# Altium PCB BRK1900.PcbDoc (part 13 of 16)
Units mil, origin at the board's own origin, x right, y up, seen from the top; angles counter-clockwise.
Board outline 8858.27 x 5905.51 mil, 10 copper layers (L1-TOP, L2-GND, L3-PWR, L4-GND, L5-PWR, L6-PWR, L7-GND, L8-SIG, L9-GND, L10-BOT), stack 48.824 mil thick; 456 components, 571 nets, 2296 pads, 2416 vias.
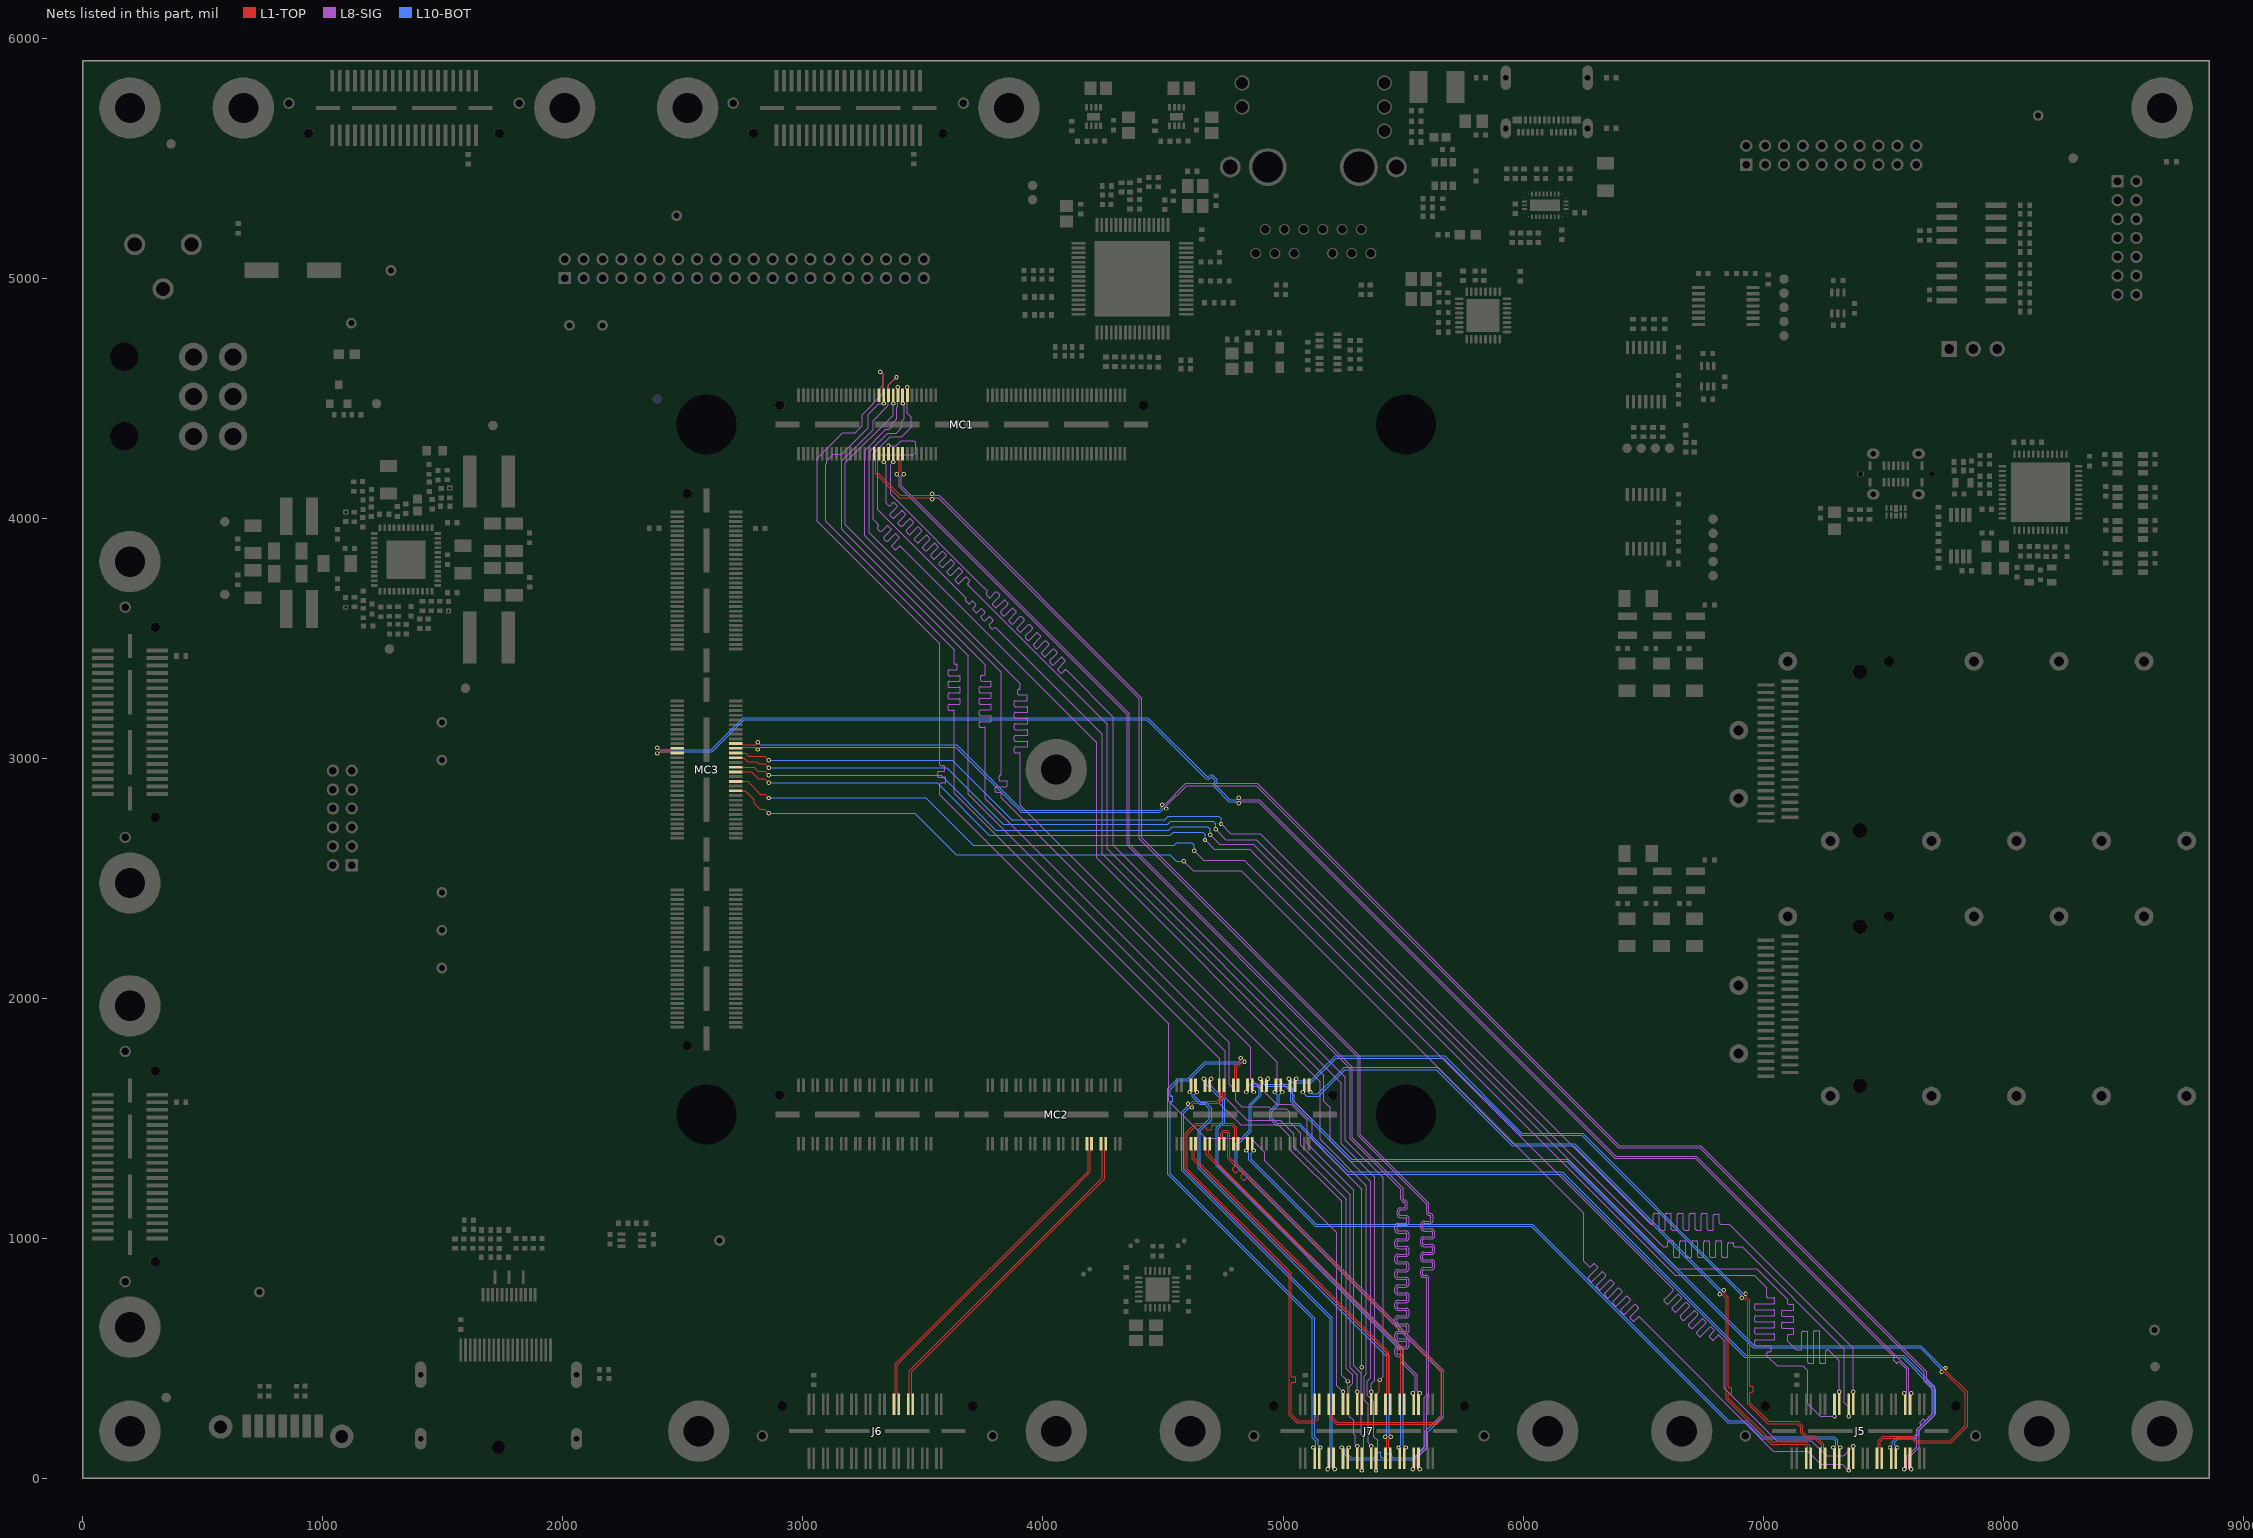
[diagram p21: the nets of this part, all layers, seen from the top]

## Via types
v1: diameter 18, hole 10, L1-TOP to L10-BOT, tented both sides, 2170 vias
v2: diameter 20, hole 10, L1-TOP to L10-BOT, tented both sides, 246 vias

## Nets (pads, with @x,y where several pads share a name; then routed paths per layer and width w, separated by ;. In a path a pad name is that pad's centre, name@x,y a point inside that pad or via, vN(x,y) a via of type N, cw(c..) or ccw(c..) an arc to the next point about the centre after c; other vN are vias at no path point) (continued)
SZG_PORTE_TX2N: J6.32 MC2.76 | length 1421.5
  L1-TOP w3.3: J6.32@3458.22,309.84 3458.22,349.17 3452.88,354.51 3452.88,445.15 4120.36,1112.64 4256.47,1248.74 4256.47,1365.8 4261.81,1371.14 MC2.76@4261.81,1394.09
SZG_PORTE_TX2P: J6.30 MC2.74 | length 1421.5
  L1-TOP w3.3: J6.30@3438.53,309.84 3438.53,349.4 3443.88,354.74 3443.88,448.88 4247.47,1252.47 4247.47,1365.74 4242.13,1371.08 MC2.74@4242.13,1394.09
SZG_PORTE_TX3N: J6.28 MC2.72 | length 1421.5
  L1-TOP w3.3: J6.28@3399.16,309.84 3399.16,349.57 3393.82,354.91 3393.82,473.09 4111.73,1191 4197.41,1276.69 4197.41,1365.35 4202.76,1370.69 MC2.72@4202.76,1394.09
SZG_PORTE_TX3P: J6.26 MC2.70 | length 1420.4
  L1-TOP w3.3: J6.26@3379.48,309.84 3379.48,349 3384.82,354.34 3384.82,451.57 ; 3384.82,452.73 3384.82,476.82 4188.41,1280.41 4188.41,1365.85 4183.07,1371.2 MC2.70@4183.07,1394.09
SZG_PORTF_C2P_CLKN: J7.36 MC1.46 | length 5620
  L1-TOP w3.3: MC1.46@3415.35,4268.11 3411.77,4264.53 3411.77,4241.56 3410.01,4239.8 3410.01,4192.39 v1@3419.29,4183.11
  L8-SIG w3.15: v1@3419.29,4183.11 3410.01,4173.83 3410.01,4133.99 4359,3185 4359,2640.73 5285.89,1713.84 5288.53,1711.2 5288.53,1419.2 5500,1207.73 5500,1188.98 5500,1164.19 ccw(c5504.63,1164.19) 5504.63,1159.56 cw(c5504.63,1145.93) 5518.26,1145.93 5518.26,1132.04 cw(c5504.63,1132.04) 5504.63,1118.41 5489.22,1118.41 ccw(c5489.22,1113.78) 5484.59,1113.78 5484.59,1099.89 ccw(c5489.22,1099.89) 5489.22,1095.26 5511.37,1095.26 cw(c5511.37,1081.63) 5525,1081.63 5525,1067.74 cw(c5511.37,1067.74) 5511.37,1054.11 5479.63,1054.11 ccw(c5479.63,1049.48) 5475,1049.48 5475,1035.59 ccw(c5479.63,1035.59) 5479.63,1030.96 5511.37,1030.96 cw(c5511.37,1017.33) 5525,1017.33 5525,1003.44 cw(c5511.37,1003.44) 5511.37,989.81 5479.63,989.81 ccw(c5479.63,985.18) 5475,985.18 5475,971.29 ccw(c5479.63,971.29) 5479.63,966.66 5511.37,966.66 cw(c5511.37,953.03) 5525,953.03 5525,939.14 cw(c5511.37,939.14) 5511.37,925.51 5479.63,925.51 ccw(c5479.63,920.88) 5475,920.88 5475,906.99 ccw(c5479.63,906.99) 5479.63,902.36 5511.37,902.36 cw(c5511.37,888.73) 5525,888.73 5525,874.84 cw(c5511.37,874.84) 5511.37,861.21 5479.63,861.21 ccw(c5479.63,856.58) 5475,856.58 5475,842.69 ccw(c5479.63,842.69) 5479.63,838.06 5511.37,838.06 cw(c5511.37,824.43) 5525,824.43 5525,810.54 cw(c5511.37,810.54) 5511.37,796.91 5479.63,796.91 ccw(c5479.63,792.28) 5475,792.28 5475,778.39 ccw(c5479.63,778.39) 5479.63,773.76 5511.37,773.76 cw(c5511.37,760.13) 5525,760.13 5525,746.24 cw(c5511.37,746.24) 5511.37,732.61 5479.63,732.61 ccw(c5479.63,727.98) 5475,727.98 5475,714.09 ccw(c5479.63,714.09) 5479.63,709.46 5511.37,709.46 cw(c5511.37,695.83) 5525,695.83 5525,681.94 cw(c5511.37,681.94) 5511.37,668.31 5479.63,668.31 ccw(c5479.63,663.68) 5475,663.68 5475,649.79 ccw(c5479.63,649.79) 5479.63,645.16 5511.37,645.16 cw(c5511.37,631.53) 5525,631.53 5525,617.64 cw(c5511.37,617.64) 5511.37,604.01 5479.63,604.01 ccw(c5479.63,599.38) 5475,599.38 5475,585.49 ccw(c5479.63,585.49) 5479.63,580.86 5511.37,580.86 cw(c5511.37,567.23) 5525,567.23 5525,553.34 cw(c5511.37,553.34) 5511.37,539.71 5479.63,539.71 ccw(c5479.63,535.08) 5475,535.08 5475,521.19 ccw(c5479.63,521.19) 5479.63,516.56 5486.37,516.56 cw(c5486.37,502.93) 5500,502.93 5500,496.85 5500,489.11 5559.17,429.93 5559.17,364.12 v1@5568.45,354.84
  other v1: 5569.55,354.84 3420.39,4183.11
SZG_PORTF_C2P_CLKP: J7.34 MC1.44 | length 5620
  L1-TOP w3.3: v1@3391.73,4183.11 3401.01,4192.39 3401.01,4240.16 3395.67,4245.5 MC1.44@3395.67,4268.11
  L8-SIG w3.15: v1@3391.73,4183.11 3401.01,4173.83 3401.01,4130.26 4350,3181.27 4350,2637 5279.53,1707.47 5279.53,1415.47 5491,1204 5491,1188.98 5491,1164.19 ccw(c5504.63,1164.19) 5504.63,1150.56 cw(c5504.63,1145.93) 5509.26,1145.93 5509.26,1132.04 cw(c5504.63,1132.04) 5504.63,1127.41 5489.22,1127.41 ccw(c5489.22,1113.78) 5475.59,1113.78 5475.59,1099.89 ccw(c5489.22,1099.89) 5489.22,1086.26 5511.37,1086.26 cw(c5511.37,1081.63) 5516,1081.63 5516,1067.74 cw(c5511.37,1067.74) 5511.37,1063.11 5479.63,1063.11 ccw(c5479.63,1049.48) 5466,1049.48 5466,1035.59 ccw(c5479.63,1035.59) 5479.63,1021.96 5511.37,1021.96 cw(c5511.37,1017.33) 5516,1017.33 5516,1003.44 cw(c5511.37,1003.44) 5511.37,998.81 5479.63,998.81 ccw(c5479.63,985.18) 5466,985.18 5466,971.29 ccw(c5479.63,971.29) 5479.63,957.66 5511.37,957.66 cw(c5511.37,953.03) 5516,953.03 5516,939.14 cw(c5511.37,939.14) 5511.37,934.51 5479.63,934.51 ccw(c5479.63,920.88) 5466,920.88 5466,906.99 ccw(c5479.63,906.99) 5479.63,893.36 5511.37,893.36 cw(c5511.37,888.73) 5516,888.73 5516,874.84 cw(c5511.37,874.84) 5511.37,870.21 5479.63,870.21 ccw(c5479.63,856.58) 5466,856.58 5466,842.69 ccw(c5479.63,842.69) 5479.63,829.06 5511.37,829.06 cw(c5511.37,824.43) 5516,824.43 5516,810.54 cw(c5511.37,810.54) 5511.37,805.91 5479.63,805.91 ccw(c5479.63,792.28) 5466,792.28 5466,778.39 ccw(c5479.63,778.39) 5479.63,764.76 5511.37,764.76 cw(c5511.37,760.13) 5516,760.13 5516,746.24 cw(c5511.37,746.24) 5511.37,741.61 5479.63,741.61 ccw(c5479.63,727.98) 5466,727.98 5466,714.09 ccw(c5479.63,714.09) 5479.63,700.46 5511.37,700.46 cw(c5511.37,695.83) 5516,695.83 5516,681.94 cw(c5511.37,681.94) 5511.37,677.31 5479.63,677.31 ccw(c5479.63,663.68) 5466,663.68 5466,649.79 ccw(c5479.63,649.79) 5479.63,636.16 5511.37,636.16 cw(c5511.37,631.53) 5516,631.53 5516,617.64 cw(c5511.37,617.64) 5511.37,613.01 5479.63,613.01 ccw(c5479.63,599.38) 5466,599.38 5466,585.49 ccw(c5479.63,585.49) 5479.63,571.86 5511.37,571.86 cw(c5511.37,567.23) 5516,567.23 5516,553.34 cw(c5511.37,553.34) 5511.37,548.71 5479.63,548.71 ccw(c5479.63,535.08) 5466,535.08 5466,521.19 ccw(c5479.63,521.19) 5479.63,507.56 5486.37,507.56 cw(c5486.37,502.93) 5491,502.93 5491,496.85 5491,485.38 5550.17,426.2 5550.17,364.12 v1@5540.89,354.84
  other v1: 5539.8,354.84 3390.63,4183.11
SZG_PORTF_P2C_CLKN: J7.35 MC1.36 | length 5622.8
  L1-TOP w3.3: MC1.36@3316.93,4268.11 3311.59,4262.77 3311.59,4188.29 3405.39,4094.49 3535.43,4094.49 3539.37,4098.43 v1(3539.37,4101.49)
  L8-SIG w3.15: v1(3539.37,4101.49) 3541.64,4101.49 3548.64,4094.49 3567.1,4094.49 4411,3250.59 4411,2667.73 5319.89,1758.84 5322.53,1756.2 5322.53,1431.2 5607,1146.73 5607,1133.86 5607,1108.31 ccw(c5611.63,1108.31) 5611.63,1103.68 cw(c5611.63,1090.05) 5625.26,1090.05 5625.26,1076.16 cw(c5611.63,1076.16) 5611.63,1062.53 5587.34,1062.53 ccw(c5587.34,1057.9) 5582.71,1057.9 5582.71,1044.01 ccw(c5587.34,1044.01) 5587.34,1039.38 5618.37,1039.38 cw(c5618.37,1025.75) 5632,1025.75 5632,1011.86 cw(c5618.37,1011.86) 5618.37,998.23 5586.63,998.23 ccw(c5586.63,993.6) 5582,993.6 5582,979.71 ccw(c5586.63,979.71) 5586.63,975.08 5618.37,975.08 cw(c5618.37,961.45) 5632,961.45 5632,947.56 cw(c5618.37,947.56) 5618.37,933.93 5586.63,933.93 ccw(c5586.63,929.3) 5582,929.3 5582,915.41 ccw(c5586.63,915.41) 5586.63,910.78 5618.37,910.78 cw(c5618.37,897.15) 5632,897.15 5632,883.26 cw(c5618.37,883.26) 5618.37,869.63 5586.63,869.63 ccw(c5586.63,865) 5582,865 5582,851.11 ccw(c5586.63,851.11) 5586.63,846.48 5593.37,846.48 cw(c5593.37,832.85) 5607,832.85 5607,826.77 5607,343.29 5598,334.29 5598,124 5593,119 5559.17,85.17 5559.17,48.14 v1@5568.45,38.86
  other v1: 5569.55,38.86
SZG_PORTF_P2C_CLKP: J7.33 MC1.34 | length 5622.8
  L1-TOP w3.3: MC1.34@3297.24,4268.11 3302.59,4262.77 3302.59,4184.56 3401.66,4085.49 3535.43,4085.49 3539.37,4081.55 v1(3539.37,4078.49)
  L8-SIG w3.15: v1(3539.37,4078.49) 3541.64,4078.49 3548.64,4085.49 3563.37,4085.49 4402,3246.86 4402,2664 5313.53,1752.47 5313.53,1427.47 5598,1143 5598,1133.86 5598,1108.31 ccw(c5611.63,1108.31) 5611.63,1094.68 cw(c5611.63,1090.05) 5616.26,1090.05 5616.26,1076.16 cw(c5611.63,1076.16) 5611.63,1071.53 5587.34,1071.53 ccw(c5587.34,1057.9) 5573.71,1057.9 5573.71,1044.01 ccw(c5587.34,1044.01) 5587.34,1030.38 5618.37,1030.38 cw(c5618.37,1025.75) 5623,1025.75 5623,1011.86 cw(c5618.37,1011.86) 5618.37,1007.23 5586.63,1007.23 ccw(c5586.63,993.6) 5573,993.6 5573,979.71 ccw(c5586.63,979.71) 5586.63,966.08 5618.37,966.08 cw(c5618.37,961.45) 5623,961.45 5623,947.56 cw(c5618.37,947.56) 5618.37,942.93 5586.63,942.93 ccw(c5586.63,929.3) 5573,929.3 5573,915.41 ccw(c5586.63,915.41) 5586.63,901.78 5618.37,901.78 cw(c5618.37,897.15) 5623,897.15 5623,883.26 cw(c5618.37,883.26) 5618.37,878.63 5586.63,878.63 ccw(c5586.63,865) 5573,865 5573,851.11 ccw(c5586.63,851.11) 5586.63,837.48 5593.37,837.48 cw(c5593.37,832.85) 5598,832.85 5598,826.77 5598,347.02 5589,338.02 5589,127.73 5550.17,88.9 5550.17,48.14 v1@5540.9,38.86
  other v1: 5539.8,38.86
SZG_PORTF_REFCLKN: J7.15 MC2.103 | length 2422.7
  L10-BOT w3.3: v1(4877.95,1609.4) 4866.7,1620.65 4866.7,1629 4871.7,1634 4890.49,1634 4900.34,1624.15 4900.34,1598.89 4859,1557.55 4859,1449.77 4800.6,1391.36 4800.6,1304.78 5661.42,443.96 5661.42,264.7 5593.1,196.38 5593.1,135.96 5543.76,86.61 5484.17,86.61 5458.36,86.61 cw(c5458.36,91.27) 5453.7,91.27 5453.7,98.07 ccw(c5449.04,98.07) 5449.04,102.73 5435.06,102.73 ccw(c5435.06,98.07) 5430.4,98.07 5430.4,91.27 cw(c5425.74,91.27) 5425.74,86.61 5411.76,86.61 cw(c5411.76,91.27) 5407.1,91.27 5407.1,103.66 ccw(c5402.44,103.66) 5402.44,108.32 5388.46,108.32 ccw(c5388.46,103.66) 5383.8,103.66 5383.8,91.27 cw(c5379.14,91.27) 5379.14,86.61 5377.49,86.61 5283.58,86.61 5263.9,106.3 5263.9,118.48 v1(5274.28,128.86)
SZG_PORTF_REFCLKP: J7.13 MC2.101 | length 2422.7
  L10-BOT w3.3: v1(4846.46,1609.4) 4857.7,1620.65 4857.7,1632.73 4867.98,1643 4894.22,1643 4909.34,1627.88 4909.34,1595.16 4868,1553.82 4868,1446.04 4809.6,1387.64 4809.6,1308.51 5670.42,447.69 5670.42,260.97 5602.1,192.65 5602.1,132.23 5547.49,77.61 5279.86,77.61 5254.9,102.57 5254.9,118.48 v1(5244.52,128.86)
SZG_PORTF_RX0N: J7.7 MC2.99 | length 2245.6
  L1-TOP w3.3: MC2.99@4812.99,1637.4 4812.99,1660.04 4807.65,1665.38 4807.65,1713.16 4833.28,1738.79 4836.86,1735.21 v1(4839.6,1735.21)
  L10-BOT w3.3: v1(4839.6,1735.21) 4837.98,1733.59 4828.08,1733.59 4822.17,1727.68 4677.81,1727.68 4606.58,1656.46 4565.91,1656.46 4529.43,1619.98 4529.43,1614.2 4529.43,1596.94 ccw(c4534.09,1596.94) 4534.09,1592.28 4536.23,1592.28 cw(c4536.23,1587.62) 4540.89,1587.62 4540.89,1573.64 cw(c4536.23,1573.64) 4536.23,1568.98 4534.09,1568.98 ccw(c4534.09,1564.32) 4529.43,1564.32 4529.43,1539.37 4529.43,1269.78 5131.05,668.17 5131.05,173.02 5145.79,158.28 5145.79,139.24 v1(5156.17,128.86)
SZG_PORTF_RX0P: J7.5 MC2.97 | length 2245.6
  L1-TOP w3.3: MC2.97@4793.31,1637.4 4793.31,1660.04 4798.65,1665.38 4798.65,1716.89 4826.91,1745.15 4823.33,1748.74 v1(4823.33,1751.47)
  L10-BOT w3.3: v1(4823.33,1751.47) 4821.72,1749.86 4821.72,1739.96 4818.44,1736.68 4674.08,1736.68 4602.86,1665.46 4562.18,1665.46 4520.43,1623.71 4520.43,1266.05 4525.7,1260.78 5122.05,664.44 5122.05,178.29 5122.05,169.29 5136.79,154.55 5136.79,139.24 v1(5126.41,128.86)
SZG_PORTF_RX1N: J7.11 MC2.95 | length 1993.2
  L1-TOP w3.3: v1(4620.23,1545.12) 4622.15,1547.04 4622.15,1556.94 4627.08,1561.87 4728.14,1561.87 4748.59,1582.32 4748.59,1609.42 4753.94,1614.76 MC2.95@4753.94,1637.4
  L10-BOT w3.3: v1(4620.23,1545.12) 4618.62,1543.51 4608.72,1543.51 4586.61,1521.4 4586.61,1287.4 5204.84,669.17 5204.84,49.24 v1(5215.22,38.86)
SZG_PORTF_RX1P: J7.9 MC2.93 | length 1993.2
  L1-TOP w3.3: v1(4603.97,1561.38) 4605.89,1563.3 4615.79,1563.3 4623.35,1570.87 4724.41,1570.87 4739.59,1586.05 4739.59,1609.42 4734.25,1614.76 MC2.93@4734.25,1637.4
  L10-BOT w3.3: v1(4603.97,1561.38) 4602.36,1559.77 4602.36,1549.87 4577.61,1525.13 4577.61,1283.67 5195.84,665.44 5195.84,49.24 v1(5185.46,38.86)
SZG_PORTF_RX2N: J7.31 MC2.91 | length 1903.2
  L10-BOT w3.3: v1(4700.79,1665.4) 4689.54,1654.15 4689.54,1645.11 4716.54,1618.11 4757.03,1577.61 4757.03,1483.15 4730,1456.11 4730,1305.43 5500.12,535.31 5500.12,138.14 v1@5509.4,128.86
  other v1: 5510.5,128.86
SZG_PORTF_RX2P: J7.29 MC2.89 | length 1903.2
  L10-BOT w3.3: v1(4669.29,1665.4) 4680.54,1654.15 4680.54,1641.38 4710.17,1611.75 4716.54,1605.38 4748.03,1573.89 4748.03,1486.87 4721,1459.84 4721,1301.71 5491.12,531.59 5491.12,138.14 v1@5481.84,128.86
  other v1: 5480.74,128.86
SZG_PORTF_RX3N: J7.27 MC2.87 | length 1924.1
  L1-TOP w3.3: J7.27@5446.41,83.86 5446.41,123.03 5441.06,128.37 5441.06,163.95 5448.06,170.95 v1(5448.06,173.23)
  L10-BOT w3.3: v1(4641.73,1609.4) 4630.48,1598.15 4630.48,1593.93 4657.48,1566.93 4677.17,1566.93 4702.64,1541.45 4702.64,1495.05 4656,1448.4 4656,1296.76 5441.54,511.22 5441.54,182.51 5448.06,175.99 v1(5448.06,173.23)
SZG_PORTF_RX3P: J7.25 MC2.85 | length 1924.5
  L1-TOP w3.3: v1(5425.06,173.23) 5425.06,170.95 5432.06,163.95 5432.06,128.37 5426.72,123.03 J7.25@5426.72,83.86
  L10-BOT w3.3: v1(4610.24,1609.4) 4621.48,1598.15 4621.48,1590.2 4651.12,1560.57 4653.75,1557.93 4673.44,1557.93 4693.64,1537.72 4693.64,1498.78 4647,1452.13 4647,1293.03 5432.54,507.49 5432.54,182.51 5425.06,175.04 v1(5425.06,173.23)
SZG_PORTF_S0: J7.14 MC1.35 | length 5617.1
  L1-TOP w4.55: MC1.35@3316.93,4511.42 3320.56,4515.05 3320.56,4541.03 3334.65,4555.12 3334.65,4598.43 v1(3322.83,4610.24)
  L8-SIG w4.05: v1(3322.83,4610.24) 3334.65,4598.43 3334.65,4519.4 3246.28,4431.03 3246.28,4384.28 3217.54,4355.54 3165.92,4355.54 3060,4249.62 3060,3987 3570.5,3476.5 3570.5,2988.75 3570.5,2973.99 ccw(c3575.31,2973.99) 3575.31,2969.18 3585.44,2969.18 cw(c3585.44,2964.37) 3590.25,2964.37 3590.25,2949.94 cw(c3585.44,2949.94) 3585.44,2945.13 3566.65,2945.13 ccw(c3566.65,2940.32) 3561.84,2940.32 3561.84,2925.89 ccw(c3566.65,2925.89) 3566.65,2921.08 3590.69,2921.08 cw(c3590.69,2916.27) 3595.5,2916.27 3595.5,2901.84 cw(c3590.69,2901.84) 3590.69,2897.03 3575.31,2897.03 ccw(c3575.31,2892.22) 3570.5,2892.22 3570.5,2866.14 3570.5,2846.82 4523.62,1893.7 4523.62,1570.87 4677.17,1417.32 4865.86,1417.32 4924,1359.19 4924,1323.68 5224,1023.68 5224,386.4 v1(5249.56,360.84)
SZG_PORTF_S1: J7.16 MC1.37 | length 5632.9
  L1-TOP w4.55: J7.16@5269.24,309.84 v1(5269.24,403.99)
  L8-SIG w4.05: v1(3336.61,4477.42) 3316,4477.42 3272,4433.42 3272,4375.72 3162.28,4266 3126,4266 3099,4239 3099,4228.51 3094.49,4224 3094.49,3987.51 3629.92,3452.08 3629.92,3437.01 3629.92,3396.96 ccw(c3634.73,3396.96) 3634.73,3392.15 3638.21,3392.15 cw(c3638.21,3387.34) 3643.02,3387.34 3643.02,3372.91 cw(c3638.21,3372.91) 3638.21,3368.1 3609.73,3368.1 ccw(c3609.73,3363.29) 3604.92,3363.29 3604.92,3348.86 ccw(c3609.73,3348.86) 3609.73,3344.05 3650.11,3344.05 cw(c3650.11,3339.24) 3654.92,3339.24 3654.92,3324.81 cw(c3650.11,3324.81) 3650.11,3320 3609.73,3320 ccw(c3609.73,3315.19) 3604.92,3315.19 3604.92,3300.76 ccw(c3609.73,3300.76) 3609.73,3295.95 3650.11,3295.95 cw(c3650.11,3291.14) 3654.92,3291.14 3654.92,3276.71 cw(c3650.11,3276.71) 3650.11,3271.9 3609.73,3271.9 ccw(c3609.73,3267.09) 3604.92,3267.09 3604.92,3252.66 ccw(c3609.73,3252.66) 3609.73,3247.85 3650.11,3247.85 cw(c3650.11,3243.04) 3654.92,3243.04 3654.92,3228.61 cw(c3650.11,3228.61) 3650.11,3223.8 3609.73,3223.8 ccw(c3609.73,3218.99) 3604.92,3218.99 3604.92,3204.56 ccw(c3609.73,3204.56) 3609.73,3199.75 3625.11,3199.75 cw(c3625.11,3194.94) 3629.92,3194.94 3629.92,3192.91 3629.92,2855.08 4736.22,1748.78 4736.22,1559.78 4823.56,1472.44 4980.31,1472.44 5027.56,1425.2 5027.56,1370.08 5244,1153.64 5244,429.23 v1(5269.24,403.99)
SZG_PORTF_S2: J7.17 MC1.39 | length 5615.9
  L1-TOP w4.55: MC1.39@3356.3,4511.42 3356.3,4553.15 v1(3389.76,4586.61)
  L8-SIG w4.05: v1(3389.76,4586.61) 3356.3,4553.15 3356.3,4470.47 3292,4406.17 3292,4369 3162,4239 3162,3954 3688.98,3427.02 3688.98,2849.02 4607,1931 4758.78,1779.22 4758.78,1585.22 4851.87,1492.13 4988.19,1492.13 5045,1435.31 5045,1381 5264,1162 5264,456.78 5289.71,431.07 5289.71,396.01 5275.59,381.89 5275.59,259.74 5293.59,241.74 5293.59,186.59 5301.49,178.69 5301.49,143.32 5308.61,136.2 v1(5308.61,134.86)
SZG_PORTF_S3: J7.18 MC1.41 | length 5581.9
  L8-SIG w4.05: v1(3375.98,4477.42) 3375.98,4428.98 3177,4230 3177,3973 3759.84,3390.16 3759.84,3377.95 3759.84,3350.14 cw(c3755.03,3350.14) 3755.03,3345.33 3745.6,3345.33 ccw(c3745.6,3340.52) 3740.79,3340.52 3740.79,3326.09 ccw(c3745.6,3326.09) 3745.6,3321.28 3780.03,3321.28 cw(c3780.03,3316.47) 3784.84,3316.47 3784.84,3302.04 cw(c3780.03,3302.04) 3780.03,3297.23 3739.65,3297.23 ccw(c3739.65,3292.42) 3734.84,3292.42 3734.84,3277.99 ccw(c3739.65,3277.99) 3739.65,3273.18 3780.03,3273.18 cw(c3780.03,3268.37) 3784.84,3268.37 3784.84,3253.94 cw(c3780.03,3253.94) 3780.03,3249.13 3739.65,3249.13 ccw(c3739.65,3244.32) 3734.84,3244.32 3734.84,3229.89 ccw(c3739.65,3229.89) 3739.65,3225.08 3780.03,3225.08 cw(c3780.03,3220.27) 3784.84,3220.27 3784.84,3205.84 cw(c3780.03,3205.84) 3780.03,3201.03 3739.65,3201.03 ccw(c3739.65,3196.22) 3734.84,3196.22 3734.84,3181.79 ccw(c3739.65,3181.79) 3739.65,3176.98 3780.03,3176.98 cw(c3780.03,3172.17) 3784.84,3172.17 3784.84,3157.74 cw(c3780.03,3157.74) 3780.03,3152.93 3739.65,3152.93 ccw(c3739.65,3148.12) 3734.84,3148.12 3734.84,3133.69 ccw(c3739.65,3133.69) 3739.65,3128.88 3755.03,3128.88 cw(c3755.03,3124.07) 3759.84,3124.07 3759.84,3122.05 3759.84,2831.16 4775.59,1815.41 4775.59,1641.41 4804,1613 4804,1574 4829,1549 4941,1549 4950,1540 5014,1540 5028,1526 5028,1483 5074,1437 5074,1388 5279.53,1182.47 5279.53,460.94 5308.61,431.86 v1(5308.61,360.84)
SZG_PORTF_S4: J7.19 MC1.43 | length 5581.9
  L8-SIG w4.05: v1(3395.67,4545.42) 3395.67,4465.6 3389.97,4459.9 3389.97,4413.59 3373,4396.62 3373,4383 3360.08,4370.08 3345.66,4370.08 3257.28,4281.7 3257.28,3926.72 3826.77,3357.23 3826.77,2960.63 3826.77,2934.19 cw(c3821.96,2934.19) 3821.96,2929.38 3821.83,2929.38 ccw(c3821.83,2924.57) 3817.02,2924.57 3817.02,2910.14 ccw(c3821.83,2910.14) 3821.83,2905.33 3846.96,2905.33 cw(c3846.96,2900.52) 3851.77,2900.52 3851.77,2886.09 cw(c3846.96,2886.09) 3846.96,2881.28 3806.58,2881.28 ccw(c3806.58,2876.47) 3801.77,2876.47 3801.77,2862.04 ccw(c3806.58,2862.04) 3806.58,2857.23 3821.96,2857.23 cw(c3821.96,2852.42) 3826.77,2852.42 3826.77,2850.39 3826.77,2835.23 4866,1796 4866,1665 4973,1558 5034,1558 5100,1492 5100,1395 5295.28,1199.72 5295.28,468.81 5326.33,437.76 5326.33,181.13 5336.71,170.75 5336.71,41.27 v1(5328.3,32.86)
SZG_PORTF_S5: J7.20 MC1.45 | length 5632.9
  L1-TOP w4.55: J7.20@5328.3,309.84 v1(5328.3,463.04)
  L8-SIG w4.05: v1(3415.35,4477.42) 3415.35,4474.83 3421.86,4468.33 3421.86,4413.98 3412,4404.13 3412,4378 3388.33,4354.33 3353.56,4354.33 3275.48,4276.25 3275.48,3939.52 3905.51,3309.49 3905.51,3304.21 3905.51,3292.31 cw(c3900.7,3292.31) 3900.7,3287.5 ccw(c3900.7,3282.69) 3895.89,3282.69 3895.89,3268.26 ccw(c3900.7,3268.26) 3900.7,3263.45 3929.47,3263.45 cw(c3929.47,3258.64) 3934.28,3258.64 3934.28,3244.21 cw(c3929.47,3244.21) 3929.47,3239.4 3885.32,3239.4 ccw(c3885.32,3234.59) 3880.51,3234.59 3880.51,3220.16 ccw(c3885.32,3220.16) 3885.32,3215.35 3932.46,3215.35 cw(c3932.46,3210.54) 3937.27,3210.54 3937.27,3196.11 cw(c3932.46,3196.11) 3932.46,3191.3 3885.32,3191.3 ccw(c3885.32,3186.49) 3880.51,3186.49 3880.51,3172.06 ccw(c3885.32,3172.06) 3885.32,3167.25 3932.46,3167.25 cw(c3932.46,3162.44) 3937.27,3162.44 3937.27,3148.01 cw(c3932.46,3148.01) 3932.46,3143.2 3885.32,3143.2 ccw(c3885.32,3138.39) 3880.51,3138.39 3880.51,3123.96 ccw(c3885.32,3123.96) 3885.32,3119.15 3932.46,3119.15 cw(c3932.46,3114.34) 3937.27,3114.34 3937.27,3099.91 cw(c3932.46,3099.91) 3932.46,3095.1 3885.32,3095.1 ccw(c3885.32,3090.29) 3880.51,3090.29 3880.51,3075.86 ccw(c3885.32,3075.86) 3885.32,3071.05 3932.46,3071.05 cw(c3932.46,3066.24) 3937.27,3066.24 3937.27,3051.81 cw(c3932.46,3051.81) 3932.46,3047 3885.32,3047 ccw(c3885.32,3042.19) 3880.51,3042.19 3880.51,3027.76 ccw(c3885.32,3027.76) 3885.32,3022.95 3900.7,3022.95 cw(c3900.7,3018.14) 3905.51,3018.14 3905.51,3016.11 3905.51,2803.49 4975,1734 4975,1667 5046,1596 5046,1570 5122,1494 5122,1410 5328.3,1203.7 v1(5328.3,463.04)
SZG_PORTF_S6: J7.21 MC1.47 | length 5581.9
  L8-SIG w4.05: v1(3435.04,4545.42) 3435.04,4436.96 3452,4420 3452,4379 3411.58,4338.58 3364.64,4338.58 3293.32,4267.26 3293.32,3994.08 3299.21,3988.19 3300.64,3986.76 3314.22,3973.19 cw(c3310.82,3969.78) 3314.22,3966.38 3310.63,3962.8 ccw(c3314.03,3959.4) 3310.63,3956 3320.84,3945.79 ccw(c3324.24,3949.19) 3327.64,3945.79 3348.9,3967.05 cw(c3352.3,3963.65) 3355.7,3967.05 3365.91,3956.85 cw(c3362.5,3953.45) 3365.91,3950.05 3337.35,3921.5 ccw(c3340.75,3918.09) 3337.35,3914.69 3347.56,3904.49 ccw(c3350.96,3907.89) 3354.36,3904.49 3382.91,3933.04 cw(c3386.31,3929.64) 3389.71,3933.04 3399.92,3922.84 cw(c3396.52,3919.44) 3399.92,3916.04 3371.36,3887.48 ccw(c3374.77,3884.08) 3371.36,3880.68 3381.57,3870.48 ccw(c3384.97,3873.88) 3388.37,3870.48 3399.25,3881.35 cw(c3402.65,3877.95) 3406.05,3881.35 3407.48,3879.92 4223,3064.4 4223,2585 5155,1653 5155,1412 5347.35,1219.65 5347.35,433.73 5338.63,425.01 5338.63,324.66 5354.1,309.19 5354.1,148.42 v1(5367.67,134.86)
SZG_PORTF_S7: J7.22 MC1.38 | length 5581.9
  L8-SIG w4.05: v1(3336.61,4234.11) 3347,4223.72 3347,4062.45 3355.57,4053.88 3357,4052.45 ccw(c3360.4,4055.85) 3363.8,4052.45 3374.68,4063.33 cw(c3378.08,4059.93) 3381.48,4063.33 3391.68,4053.12 cw(c3388.28,4049.72) 3391.68,4046.32 3363.13,4017.77 ccw(c3366.53,4014.37) 3363.13,4010.97 3373.33,4000.76 ccw(c3376.73,4004.16) 3380.13,4000.76 3408.69,4029.32 cw(c3412.09,4025.91) 3415.49,4029.31 3425.69,4019.11 cw(c3422.29,4015.71) 3425.69,4012.31 3397.14,3983.76 ccw(c3400.54,3980.35) 3397.14,3976.95 3407.34,3966.75 ccw(c3410.74,3970.15) 3414.15,3966.75 3442.7,3995.3 cw(c3446.1,3991.9) 3449.5,3995.3 3459.7,3985.1 cw(c3456.3,3981.7) 3459.7,3978.3 3431.15,3949.74 ccw(c3434.55,3946.34) 3431.15,3942.94 3441.36,3932.74 ccw(c3444.76,3936.14) 3448.16,3932.74 3476.71,3961.29 cw(c3480.11,3957.89) 3483.51,3961.29 3493.72,3951.09 cw(c3490.32,3947.69) 3493.72,3944.29 3465.16,3915.73 ccw(c3468.56,3912.33) 3465.16,3908.93 3475.37,3898.73 ccw(c3478.77,3902.13) 3482.17,3898.73 3510.72,3927.28 cw(c3514.12,3923.88) 3517.52,3927.28 3527.73,3917.08 cw(c3524.33,3913.67) 3527.73,3910.27 3499.18,3881.72 ccw(c3502.58,3878.32) 3499.18,3874.92 3509.38,3864.71 ccw(c3512.78,3868.12) 3516.18,3864.71 3544.73,3893.27 cw(c3548.14,3889.87) 3551.54,3893.27 3561.74,3883.06 cw(c3558.34,3879.66) 3561.74,3876.26 3533.19,3847.71 ccw(c3536.59,3844.31) 3533.19,3840.91 3543.39,3830.7 ccw(c3546.79,3834.1) 3550.19,3830.7 3578.75,3859.26 cw(c3582.15,3855.85) 3585.55,3859.26 3595.75,3849.05 cw(c3592.35,3845.65) 3595.75,3842.25 3567.2,3813.7 ccw(c3570.6,3810.3) 3567.2,3806.89 3577.4,3796.69 ccw(c3580.8,3800.09) 3584.2,3796.69 3612.76,3825.24 cw(c3616.16,3821.84) 3619.56,3825.24 3629.76,3815.04 cw(c3626.36,3811.64) 3629.76,3808.24 3601.21,3779.68 ccw(c3604.61,3776.28) 3601.21,3772.88 3611.41,3762.68 ccw(c3614.82,3766.08) 3618.22,3762.68 3646.77,3791.23 cw(c3650.17,3787.83) 3653.57,3791.23 3663.78,3781.03 cw(c3660.37,3777.63) 3663.78,3774.23 3635.22,3745.67 ccw(c3638.62,3742.27) 3635.22,3738.87 3645.43,3728.67 ccw(c3648.83,3732.07) 3652.23,3728.67 ; 3652.23,3728.67 3676.46,3752.9 cw(c3679.87,3749.5) 3683.27,3752.9 3693.47,3742.7 cw(c3690.07,3739.3) 3693.47,3735.9 3686.91,3729.34 ccw(c3690.31,3725.94) 3686.91,3722.54 3716.18,3693.27 3717.61,3691.84 4267,3142.45 4267,2623 5243,1647 5243,1394 5382.25,1254.75 5382.25,409.09 5367.67,394.5 v1(5367.67,360.84)
SZG_PORTF_S8: J7.23 MC1.40 | length 5581.9
  L8-SIG w4.05: v1(3356.3,4302.11) 3388.72,4302.11 3409.45,4322.83 3461.78,4322.83 3469.08,4315.53 3469.08,4272.22 3460.63,4263.78 3321.39,4263.78 3310.82,4253.21 3310.82,4035.64 3661.42,3685.04 3662.85,3683.61 3677.93,3668.53 cw(c3674.53,3665.13) 3677.93,3661.73 ccw(c3681.33,3658.32) 3677.93,3654.92 3688.13,3644.72 ccw(c3691.53,3648.12) 3694.93,3644.72 3702.4,3652.19 cw(c3705.8,3648.79) 3709.2,3652.19 3719.41,3641.98 cw(c3716.01,3638.58) 3719.41,3635.18 3708.93,3624.7 ccw(c3712.33,3621.3) 3708.93,3617.9 3719.13,3607.7 ccw(c3722.53,3611.1) 3725.93,3607.7 3739.46,3621.22 cw(c3742.86,3617.82) 3746.27,3621.22 3756.47,3611.02 cw(c3753.07,3607.62) 3756.47,3604.22 3742.94,3590.69 ccw(c3746.34,3587.29) 3742.94,3583.89 3753.14,3573.68 ccw(c3756.55,3577.08) 3759.95,3573.68 3773.48,3587.21 cw(c3776.88,3583.81) 3780.28,3587.21 3790.48,3577.01 cw(c3787.08,3573.61) 3790.48,3570.21 3776.95,3556.68 ccw(c3780.35,3553.28) 3776.95,3549.88 3787.16,3539.67 ccw(c3790.56,3543.07) 3793.96,3539.67 3796.97,3542.68 cw(c3800.37,3539.28) 3803.77,3542.68 3805.2,3541.25 4246,3100.46 4246,2603 5170,1679 5170,1571 5196,1545 5196,1405 5364.79,1236.21 5364.79,419.91 5350.08,405.2 5350.08,345.7 5378.59,317.2 5378.59,174.45 5393.7,159.34 5393.7,78.74 5387.35,72.39 v1(5387.35,32.86)
SZG_PORTF_S9: J7.24 MC1.42 | length 5634.8
  L1-TOP w4.55: J7.24@5387.35,309.84 5387.35,349.02 5401.57,363.24 5401.57,409.45 v1(5402.36,410.23)
  L8-SIG w4.05: v1(3375.98,4234.11) 3366,4224.13 3366,4098.57 3751.97,3712.6 3753.4,3711.17 3767.43,3697.14 cw(c3764.03,3693.73) 3767.43,3690.33 3764.73,3687.64 ccw(c3768.13,3684.23) 3764.73,3680.83 3774.94,3670.63 ccw(c3778.34,3674.03) 3781.74,3670.63 3802.11,3691.01 cw(c3805.52,3687.6) 3808.92,3691.01 3819.12,3680.8 cw(c3815.72,3677.4) 3819.12,3674 3790.57,3645.45 ccw(c3793.97,3642.04) 3790.57,3638.64 3800.77,3628.44 ccw(c3804.17,3631.84) 3807.57,3628.44 3836.13,3656.99 cw(c3839.53,3653.59) 3842.93,3656.99 3853.13,3646.79 cw(c3849.73,3643.39) 3853.13,3639.99 3824.58,3611.43 ccw(c3827.98,3608.03) 3824.58,3604.63 3834.78,3594.43 ccw(c3838.18,3597.83) 3841.59,3594.43 3870.14,3622.98 cw(c3873.54,3619.58) 3876.94,3622.98 3887.14,3612.78 cw(c3883.74,3609.38) 3887.14,3605.98 3858.59,3577.42 ccw(c3861.99,3574.02) 3858.59,3570.62 3868.8,3560.42 ccw(c3872.2,3563.82) 3875.6,3560.42 3904.15,3588.97 cw(c3907.55,3585.57) 3910.95,3588.97 3921.16,3578.77 cw(c3917.76,3575.36) 3921.16,3571.96 3892.6,3543.41 ccw(c3896,3540.01) 3892.6,3536.61 3902.81,3526.4 ccw(c3906.21,3529.81) 3909.61,3526.4 3938.16,3554.96 cw(c3941.56,3551.56) 3944.96,3554.96 3955.17,3544.75 cw(c3951.77,3541.35) 3955.17,3537.95 3926.62,3509.4 ccw(c3930.02,3506) 3926.62,3502.6 3936.82,3492.39 ccw(c3940.22,3495.79) 3943.62,3492.39 3972.17,3520.95 cw(c3975.58,3517.54) 3978.98,3520.95 3989.18,3510.74 cw(c3985.78,3507.34) 3989.18,3503.94 3960.63,3475.39 ccw(c3964.03,3471.99) 3960.63,3468.58 3970.83,3458.38 ccw(c3974.23,3461.78) 3977.63,3458.38 4006.19,3486.93 cw(c4009.59,3483.53) 4012.99,3486.93 4023.19,3476.73 cw(c4019.79,3473.33) 4023.19,3469.93 3994.64,3441.38 ccw(c3998.04,3437.97) 3994.64,3434.57 4004.84,3424.37 ccw(c4008.24,3427.77) 4011.64,3424.37 4040.2,3452.92 cw(c4043.6,3449.52) 4047,3452.92 4057.2,3442.72 cw(c4053.8,3439.32) 4057.2,3435.92 4028.65,3407.36 ccw(c4032.05,3403.96) 4028.65,3400.56 4038.85,3390.36 ccw(c4042.26,3393.76) 4045.66,3390.36 4074.21,3418.91 cw(c4077.61,3415.51) 4081.01,3418.91 4091.22,3408.71 cw(c4087.81,3405.31) 4091.22,3401.9 4062.66,3373.35 ccw(c4066.06,3369.95) 4062.66,3366.55 4072.87,3356.35 ccw(c4076.27,3359.75) 4079.67,3356.35 4090.54,3367.22 cw(c4093.94,3363.82) 4097.35,3367.22 4098.78,3365.79 4293.5,3171.07 4293.5,2636.5 5259.84,1670.16 5259.84,1409.16 5417.32,1251.68 5417.32,425.2 v1(5402.36,410.23)
SZG_PORTF_TX0N: J7.8 MC2.100 | length 1867.5
  L1-TOP w3.3: MC2.100@4812.99,1394.09 4812.99,1417.03 4807.65,1422.37 4807.65,1432.73 4807.65,1461.54 4789.5,1479.69 4635.96,1479.69 4610.06,1453.78 4592,1435.73 4592,1285.04 5025,852.04 5025,263.27 5057.27,231 5127.73,231 5145.79,249.06 5145.79,265.14 5151.13,270.48 J7.8@5151.13,309.84
SZG_PORTF_TX0P: J7.6 MC2.98 | length 1867.5
  L1-TOP w3.3: MC2.98@4793.31,1394.09 4793.31,1416.67 4798.65,1422.01 4798.65,1457.81 4785.77,1470.69 4737.34,1470.69 4707.18,1470.69 ccw(c4707.18,1466.03) 4702.52,1466.03 4702.52,1456.54 cw(c4697.86,1456.54) 4697.86,1451.88 4683.88,1451.88 cw(c4683.88,1456.54) 4679.22,1456.54 4679.22,1466.03 ccw(c4674.56,1466.03) 4674.56,1470.69 4649.61,1470.69 4639.69,1470.69 4601,1432 4601,1288.76 5034,855.76 5034,456.69 5034,427.65 ccw(c5038.66,427.65) 5038.66,422.99 5048.35,422.99 cw(c5048.35,418.33) 5053.01,418.33 5053.01,404.35 cw(c5048.35,404.35) 5048.35,399.69 5038.66,399.69 ccw(c5038.66,395.03) 5034,395.03 5034,370.08 5034,267 5061,240 5124,240 5136.79,252.79 5136.79,264.74 5131.45,270.09 J7.6@5131.45,309.84
SZG_PORTF_TX1N: J7.12 MC2.96 | length 2202.8
  L1-TOP w3.3: MC2.96@4753.94,1394.09 4753.94,1416.88 4748.59,1422.22 4748.59,1434.59 4755,1441 4763,1441 4769,1435 4769,1334 4779.85,1323.15 4797.49,1305.51 cw(c4794.19,1302.22) 4797.49,1298.92 4789.91,1291.34 ccw(c4793.21,1288.05) 4789.91,1284.75 4799.8,1274.87 ccw(c4803.09,1278.16) 4806.39,1274.87 4813.96,1282.45 cw(c4817.26,1279.15) 4820.56,1282.45 4830.44,1272.56 cw(c4827.15,1269.26) 4830.44,1265.97 4824.45,1259.98 ccw(c4827.75,1256.69) 4824.45,1253.39 4834.34,1243.51 ccw(c4837.64,1246.8) 4840.93,1243.51 4846.92,1249.49 cw(c4850.21,1246.2) 4853.51,1249.49 4870.4,1232.6 5660,443 5660,259 5636,235 5225.84,235 5204.84,256 5204.84,264.72 5210.19,270.06 J7.12@5210.19,309.84
SZG_PORTF_TX1P: J7.10 MC2.94 | length 2202.8
  L1-TOP w3.3: MC2.94@4734.25,1394.09 4734.25,1416.66 4739.59,1422 4739.59,1438.32 4751.27,1450 4766.73,1450 4778,1438.73 4778,1337.73 5669,446.73 5669,255.27 5639.73,226 5222.12,226 5195.84,252.27 5195.84,265.46 5190.5,270.8 J7.10@5190.5,309.84
SZG_PORTF_TX2N: J7.32 MC2.92 | length 1424.4
  L1-TOP w3.3: MC2.92@4694.88,1394.09 4694.88,1371.18 4689.54,1365.84 4689.54,1352.46 4714,1328 5500.12,541.88 5500.12,354.26 5505.46,348.92 J7.32@5505.46,309.84
SZG_PORTF_TX2P: J7.30 MC2.90 | length 1424.4
  L1-TOP w3.3: MC2.90@4675.2,1394.09 4675.2,1371.09 4680.54,1365.75 4680.54,1348.73 5491.12,538.15 5491.12,354.2 5485.78,348.86 J7.30@5485.78,309.84
SZG_PORTF_TX3N: J7.28 MC2.88 | length 1424.4
  L1-TOP w3.3: MC2.88@4635.83,1394.09 4635.83,1371.34 4630.48,1366 4630.48,1335.52 5441.06,524.94 5441.06,354.03 5446.41,348.69 J7.28@5446.41,309.84
SZG_PORTF_TX3P: J7.26 MC2.86 | length 1424.4
  L1-TOP w3.3: MC2.86@4616.14,1394.09 4616.14,1371.26 4621.48,1365.91 4621.48,1331.79 5432.06,521.21 5432.06,354.59 5426.72,349.25 J7.26@5426.72,309.84
SZG_PORTG_C2P_CLKN: J5.36 MC3.99 | length 6630
  L1-TOP w3.3: v1(2393.7,3043) 2394.57,3043 2401.57,3036 2448.79,3036 2454.13,3041.34 MC3.99@2476.77,3041.34
  L8-SIG w3.15: v1(4814.96,2834.9) 4814.96,2831.83 4818.9,2827.9 4900.45,2827.9 6386.11,1342.24 6721.67,1342.24 7278.02,785.89 7606.42,457.49 7606.42,356.69 7608.26,354.84 v1(7616.8,354.84)
  L10-BOT w3.3: v1(2393.7,3043) 2395.98,3043 2402.98,3036 2618.96,3036 2752.26,3169.29 4437.01,3169.29 4679.13,2927.17 4682.16,2924.13 4683.48,2922.82 ccw(c4686.78,2926.11) 4690.07,2922.82 4692.66,2925.41 cw(c4702.29,2915.72) 4711.95,2925.37 4721.83,2915.49 cw(c4712.18,2905.83) 4721.83,2896.17 4719.28,2893.61 ccw(c4722.57,2890.32) 4719.28,2887.02 4748.94,2857.36 4751.97,2854.33 4778.4,2827.9 4805.68,2827.9 4812.68,2834.9 v1(4814.96,2834.9)
SZG_PORTG_C2P_CLKP: J5.34 MC3.97 | length 6630
  L1-TOP w3.3: v1(2393.7,3020) 2394.57,3020 2401.57,3027 2448.79,3027 2454.13,3021.65 MC3.97@2476.77,3021.65
  L8-SIG w3.15: v1(4814.96,2811.9) 4814.96,2814.96 4818.9,2818.9 4896.72,2818.9 6382.38,1333.24 6717.94,1333.24 7265.29,785.89 7271.65,779.53 7527.56,523.62 7528.67,522.51 7545.04,506.14 cw(c7541.77,502.86) 7545.04,499.59 7543.51,498.06 ccw(c7546.78,494.78) 7543.51,491.51 7553.33,481.69 ccw(c7556.6,484.96) 7559.88,481.69 7561.41,483.22 cw(c7564.69,479.95) 7567.96,483.22 7581.56,469.62 7582.68,468.5 7597.42,453.76 7597.42,356.69 7595.57,354.84 v1(7587.04,354.84)
  L10-BOT w3.3: v1(2393.7,3020) 2395.98,3020 2402.98,3027 2622.69,3027 2755.99,3160.29 4433.28,3160.29 4672.77,2920.8 4675.8,2917.77 4677.12,2916.45 ccw(c4686.78,2926.11) 4696.44,2916.45 4698.99,2919.01 cw(c4702.29,2915.72) 4705.58,2919.01 4715.47,2909.12 cw(c4712.18,2905.83) 4715.47,2902.53 4712.91,2899.98 ccw(c4722.57,2890.32) 4712.94,2880.63 4742.57,2851 4745.6,2847.97 4774.67,2818.9 4805.68,2818.9 4812.68,2811.9 v1(4814.96,2811.9)
SZG_PORTG_P2C_CLKN: J5.35 MC3.102 | length 6628.1
  L1-TOP w3.3: MC3.102@2720.08,3061.02 2742.72,3061.02 2748.06,3055.68 2795.3,3055.68 2795.35,3055.63 2803.25,3055.63 2812.32,3064.7 v1@2812.32,3064.96
  L8-SIG w3.15: v1(4496.56,2806.59) 4498.17,2808.19 4508.07,2808.19 4512.57,2812.7 4594.7,2894.83 4891.58,2894.83 6400.58,1385.83 6740.16,1385.83 7680.59,445.39 7680.59,409.12 7718.22,371.49 7718.22,270.16 7649.61,201.55 7649.61,129.04 7606.42,85.86 7606.42,40.7 7608.26,38.86 v1(7616.8,38.86)
  L10-BOT w3.3: v1(2812.32,3065.96) 2822.65,3055.63 3641.22,3055.63 3913.51,2783.34 4483.21,2783.34 4487.73,2787.86 4494.95,2795.08 4494.95,2804.98 v1(4496.56,2806.59)
SZG_PORTG_P2C_CLKP: J5.33 MC3.100 | length 6628
  L1-TOP w3.3: MC3.100@2720.08,3041.34 2742.72,3041.34 2748.06,3046.68 2784.25,3046.68 2784.3,3046.63 2803.25,3046.63 2812.32,3037.56 v1@2812.32,3037.4
  L8-SIG w3.15: v1(4512.82,2790.33) 4514.43,2791.93 4514.43,2801.83 4516.29,2803.7 4598.43,2885.83 4887.85,2885.83 6396.85,1376.83 6736.43,1376.83 7671.59,441.66 7671.59,405.39 7709.22,367.77 7709.22,273.89 7696.01,260.68 7678.53,243.2 cw(c7675.26,246.47) 7671.98,243.2 7670.45,244.73 ccw(c7667.17,241.46) 7663.9,244.73 7654.08,234.91 ccw(c7657.35,231.64) 7654.08,228.36 7655.61,226.83 cw(c7652.34,223.55) 7655.61,220.28 7642.65,207.31 7640.61,205.27 7640.61,132.77 7597.42,89.58 7597.42,40.7 7595.57,38.86 v1(7587.04,38.86)
  L10-BOT w3.3: v1(2812.32,3036.3) 2822.65,3046.63 3637.49,3046.63 3909.79,2774.34 4486.93,2774.34 4496.73,2784.13 4501.31,2788.71 4511.21,2788.71 v1(4512.82,2790.33)
SZG_PORTG_REFCLKN: J5.15 MC2.104 | length 3004.2
  L10-BOT w3.3: v1(4877.95,1366.09) 4866.7,1354.85 4866.7,1330.15 4944.88,1251.97 5137.8,1059.06 6037.43,1059.06 6856.33,240.16 6932.76,240.16 6998.56,174.35 7295.07,174.35 7297.7,171.72 7311.14,158.28 7311.14,139.24 v1(7321.52,128.86)
SZG_PORTG_REFCLKP: J5.13 MC2.102 | length 3004.2
  L10-BOT w3.3: v1(4846.46,1366.09) 4857.7,1354.85 4857.7,1326.42 4938.52,1245.6 4944.88,1239.24 5134.07,1050.06 6033.7,1050.06 6852.6,231.16 6929.03,231.16 6994.84,165.35 7291.34,165.35 7302.14,154.55 7302.14,139.24 v1(7291.76,128.86)
SZG_PORTG_RX0N: J5.7 MC2.119 | length 3108.7
  L1-TOP w3.3: v1(6835.13,783.95) 6836.75,782.34 6836.75,772.44 6855.46,753.73 6855.46,383.99 6855.46,382.34 ccw(c6860.12,382.34) 6860.12,377.68 6864.95,377.68 cw(c6864.95,373.02) 6869.61,373.02 6869.61,359.04 cw(c6864.95,359.04) 6864.95,354.38 6860.12,354.38 ccw(c6860.12,349.72) 6855.46,349.72 6855.46,342.52 6855.46,333.52 7037.12,151.86 7179.76,151.86 7182.4,149.22 7193.03,138.59 7193.03,128.37 7198.38,123.03 J5.7@7198.38,83.86
  L10-BOT w3.3: v1(5114.17,1609.4) 5116.36,1609.4 5124.08,1601.68 5140.45,1601.68 5144.95,1601.68 5165.79,1622.52 5200.72,1657.44 5238.27,1695 5255.27,1712 5642.33,1712 5959.5,1394.83 6214.36,1394.83 6824.48,784.7 6834.38,784.7 v1(6835.13,783.95)
SZG_PORTG_RX0P: J5.5 MC2.117 | length 3108.7
  L1-TOP w3.3: v1(6818.87,767.69) 6820.48,766.07 6830.38,766.07 6846.46,750 6846.46,329.79 7033.39,142.86 7176.04,142.86 7184.03,134.86 7184.03,128.37 7178.69,123.03 J5.5@7178.69,83.86
  L10-BOT w3.3: v1(5082.68,1609.4) 5099.4,1592.68 5135.29,1592.68 5148.68,1592.68 5259,1703 5638.6,1703 5955.78,1385.83 6210.63,1385.83 6818.12,778.34 6818.12,768.44 v1(6818.87,767.69)
SZG_PORTG_RX1N: J5.11 MC2.115 | length 3263.3
  L1-TOP w3.3: v1(6926.67,769.19) 6928.28,767.57 6928.28,757.67 6941.4,744.55 6944.04,741.92 6944.04,389.39 6944.04,387.73 ccw(c6948.7,387.73) 6948.7,383.07 6953.54,383.07 cw(c6953.54,378.41) 6958.2,378.41 6958.2,364.43 cw(c6953.54,364.43) 6953.54,359.77 6948.7,359.77 ccw(c6948.7,355.11) 6944.04,355.11 6944.04,334.65 6944.04,315.8 7022.5,237.35 7145.46,237.35 7148.1,234.71 7165.28,217.53 7165.28,193.57 7180.26,178.58 7215.35,178.58 7252.09,141.85 7252.09,128.37 7257.43,123.03 J5.11@7257.43,83.86
  L10-BOT w3.3: v1(5055.12,1665.4) 5063.52,1657 5114.27,1657 5134.64,1677.37 5171.37,1714.1 5206.27,1749 5217.27,1760 5673.07,1760 5995.09,1437.98 6247.98,1437.98 6863.71,822.25 6915.15,770.8 6925.05,770.8 v1(6926.67,769.19)
SZG_PORTG_RX1P: J5.9 MC2.113 | length 3263.3
  L1-TOP w3.3: v1(6910.4,752.92) 6912.02,751.31 6921.92,751.31 6935.04,738.19 6935.04,312.08 7018.77,228.35 7141.73,228.35 7156.28,213.8 7156.28,189.84 7176.53,169.58 7211.62,169.58 7243.09,138.12 7243.09,128.37 7237.75,123.03 J5.9@7237.75,83.86
  L10-BOT w3.3: v1(5023.62,1665.4) 5041.02,1648 5118,1648 5221,1751 5669.34,1751 5991.37,1428.98 6244.25,1428.98 6860.52,812.7 6908.79,764.44 6908.79,754.54 v1(6910.4,752.92)
SZG_PORTG_RX2N: J5.31 MC2.111 | length 3714.1
  L10-BOT w3.3: v1(4996.06,1609.4) 4984.81,1598.15 4984.81,1558.21 4953.88,1527.28 4953.88,1502.81 4976.38,1480.32 5068.11,1480.32 5271.43,1277 5460.63,1277 6162.74,1277 6926.81,512.94 7582.47,512.94 7713.72,381.68 7713.72,263.99 7650.73,201 7650.73,185.25 7630.84,165.35 7562.99,165.35 7547.36,149.73 7547.36,139.24 v1(7557.74,128.86)
SZG_PORTG_RX2P: J5.29 MC2.109 | length 3714.1
  L10-BOT w3.3: v1(4964.57,1609.4) 4975.81,1598.15 4975.81,1561.94 4944.88,1531.01 4944.88,1499.08 4972.65,1471.32 5064.38,1471.32 5267.7,1268 5460.63,1268 6159.01,1268 6923.08,503.94 7578.74,503.94 7704.72,377.95 7704.72,267.72 7641.73,204.72 7641.73,188.98 7627.11,174.35 7559.26,174.35 7538.36,153.45 7538.36,139.24 v1(7527.98,128.86)
SZG_PORTG_RX3N: J5.27 MC2.107 | length 4132.3
  L1-TOP w3.3: J5.27@7493.65,83.86 7493.65,123.03 7488.31,128.37 7488.31,152.68 7502.03,166.4 7621,166.4 7629.92,157.48 7638.92,148.48 7783.26,148.48 7851.52,216.74 7851.52,358.06 7758.33,451.25 7758.33,459.12 v1(7759.35,460.13)
  L10-BOT w3.3: v1(4937.01,1665.4) 4925.76,1654.15 4925.76,1649.61 4933.63,1641.73 5020.6,1641.73 5037.86,1624.47 5040.5,1621.84 5040.5,1574.86 5285.36,1330 5460.63,1330 6184.7,1330 6962.39,552.31 7657.27,552.31 7747.83,461.75 7757.73,461.75 v1(7759.35,460.13)
SZG_PORTG_RX3P: J5.25 MC2.105 | length 4132.3
  L1-TOP w3.3: J5.25@7473.97,83.86 7473.97,123.03 7479.31,128.37 7479.31,156.41 7498.3,175.4 7624.73,175.4 7642.65,157.48 7779.53,157.48 7842.52,220.47 7842.52,354.33 7751.97,444.88 7744.09,444.88 v1(7743.08,443.87)
  L10-BOT w3.3: v1(4905.51,1665.4) 4916.76,1654.15 4916.76,1645.88 4929.91,1632.73 5016.87,1632.73 5031.5,1618.11 5031.5,1571.13 5281.63,1321 6180.97,1321 6958.66,543.31 7653.54,543.31 7741.47,455.38 7741.47,445.48 v1(7743.08,443.87)
SZG_PORTG_S0: J5.14 MC3.90 | length 6621.1
  L1-TOP w4: MC3.90@2720.08,2942.91 2785.12,2942.91 2814.21,2913.82 2841.77,2913.82 v1(2858.27,2897.32)
  L8-SIG w5: v1(4675.02,2659.39) 4714.39,2620.02 4860.3,2620.02 6633.86,846.46 6962.62,846.46 7015.75,793.33 7015.75,759.84 7015.75,757.34 ccw(c7020.75,757.34) 7020.75,752.34 7042.85,752.34 cw(c7042.85,747.34) 7047.85,747.34 7047.85,732.34 cw(c7042.85,732.34) 7042.85,727.34 6968.9,727.34 ccw(c6968.9,722.34) 6963.9,722.34 6963.9,707.34 ccw(c6968.9,707.34) 6968.9,702.34 7042.85,702.34 cw(c7042.85,697.34) 7047.85,697.34 7047.85,682.34 cw(c7042.85,682.34) 7042.85,677.34 6968.9,677.34 ccw(c6968.9,672.34) 6963.9,672.34 6963.9,657.34 ccw(c6968.9,657.34) 6968.9,652.34 7042.85,652.34 cw(c7042.85,647.34) 7047.85,647.34 7047.85,632.34 cw(c7042.85,632.34) 7042.85,627.34 6968.9,627.34 ccw(c6968.9,622.34) 6963.9,622.34 6963.9,607.34 ccw(c6968.9,607.34) 6968.9,602.34 7042.85,602.34 cw(c7042.85,597.34) 7047.85,597.34 7047.85,582.34 cw(c7042.85,582.34) 7042.85,577.34 6968.9,577.34 ccw(c6968.9,572.34) 6963.9,572.34 6963.9,557.34 ccw(c6968.9,557.34) 6968.9,552.34 7027.97,552.34 cw(c7027.97,547.34) 7032.97,547.34 7032.97,532.34 cw(c7027.97,532.34) 7027.97,527.34 7020.75,527.34 ccw(c7020.75,522.34) 7015.75,522.34 7015.75,512.8 7015.75,511.81 7059.06,468.5 7165.35,468.5 7185.04,448.82 7185.04,311.02 7237.22,258.84 v1(7296.8,258.84)
  L10-BOT w4: v1(2858.27,2897.32) 3559.56,2897.32 3777.11,2679.77 4530.17,2679.77 4542.45,2692.06 4665.68,2692.06 4675.02,2682.72 v1(4675.02,2659.39)
SZG_PORTG_S1: J5.16 MC3.92 | length 6621.1
  L1-TOP w4: MC3.92@2720.08,2962.6 2796.93,2962.6 2814.21,2945.32 2841.77,2945.32 v1(2858.27,2928.82)
  L8-SIG w5: v1(4697.3,2681.66) 4736.67,2642.29 4875.4,2642.29 6643.68,874.02 6972.44,874.02 7102.36,744.09 7102.36,732.28 7102.36,729.78 ccw(c7107.36,729.78) 7107.36,724.78 7122.36,724.78 cw(c7122.36,719.78) 7127.36,719.78 7127.36,704.78 cw(c7122.36,704.78) 7122.36,699.78 7082.36,699.78 ccw(c7082.36,694.78) 7077.36,694.78 7077.36,679.78 ccw(c7082.36,679.78) 7082.36,674.78 7122.36,674.78 cw(c7122.36,669.78) 7127.36,669.78 7127.36,654.78 cw(c7122.36,654.78) 7122.36,649.78 7082.36,649.78 ccw(c7082.36,644.78) 7077.36,644.78 7077.36,629.78 ccw(c7082.36,629.78) 7082.36,624.78 7122.36,624.78 cw(c7122.36,619.78) 7127.36,619.78 7127.36,604.78 cw(c7122.36,604.78) 7122.36,599.78 7107.36,599.78 ccw(c7107.36,594.78) 7102.36,594.78 7102.36,578.74 7102.36,570.87 7137.8,535.43 7141.73,535.43 7156.14,535.43 ccw(c7156.14,540.43) 7161.14,540.43 7161.14,608.09 cw(c7166.14,608.09) 7166.14,613.09 7181.14,613.09 cw(c7181.14,608.09) 7186.14,608.09 7186.14,484.04 ccw(c7191.14,484.04) 7191.14,479.04 7206.14,479.04 ccw(c7206.14,484.04) 7211.14,484.04 7211.14,610.49 cw(c7216.14,610.49) 7216.14,615.49 7231.14,615.49 cw(c7231.14,610.49) 7236.14,610.49 7236.14,484.04 ccw(c7241.14,484.04) 7241.14,479.04 7256.14,479.04 ccw(c7256.14,484.04) 7261.14,484.04 7261.14,530.43 cw(c7266.14,530.43) 7266.14,535.43 7268.64,535.43 7271.65,535.43 7316.49,490.6 v1(7316.49,360.84)
  L10-BOT w4: v1(2858.27,2928.82) 3575.31,2928.82 3803.34,2700.79 4523.62,2700.79 4538.19,2715.36 4686.93,2715.36 4697.3,2704.99 v1(4697.3,2681.66)
SZG_PORTG_S2: J5.17 MC3.82 | length 6621.1
  L1-TOP w4: MC3.82@2720.08,2864.17 2759.99,2864.17 2796.98,2827.19 2796.98,2813.26 2822.4,2787.83 2841.77,2787.83 v1(2858.27,2771.34)
  L8-SIG w4: v1(4585.94,2570.31) 4625.31,2530.94 4826.31,2530.94 6251.97,1105.28 6251.97,905.15 6273.52,883.6 6274.94,882.18 ccw(c6278.33,885.58) 6281.73,882.18 6292.62,893.07 cw(c6296.01,889.68) 6299.4,893.07 6309.59,882.89 cw(c6306.19,879.5) 6309.59,876.1 6271.92,838.44 ccw(c6275.32,835.05) 6271.92,831.65 6282.11,821.47 ccw(c6285.5,824.87) 6288.89,821.47 6326.56,859.13 cw(c6329.95,855.74) 6333.35,859.13 6343.53,848.95 cw(c6340.13,845.56) 6343.53,842.16 6305.87,804.5 ccw(c6309.26,801.11) 6305.87,797.71 6316.05,787.53 ccw(c6319.44,790.92) 6322.84,787.53 6360.5,825.19 cw(c6363.89,821.8) 6367.29,825.19 6377.47,815.01 cw(c6374.07,811.62) 6377.47,808.22 6339.81,770.56 ccw(c6343.2,767.17) 6339.81,763.77 6349.99,753.59 ccw(c6353.38,756.98) 6356.78,753.59 6394.44,791.25 cw(c6397.83,787.86) 6401.23,791.25 6411.41,781.07 cw(c6408.02,777.67) 6411.41,774.28 6373.75,736.62 ccw(c6377.14,733.22) 6373.75,729.83 6383.93,719.65 ccw(c6387.32,723.04) 6390.72,719.65 6428.38,757.31 cw(c6431.77,753.92) 6435.17,757.31 6445.35,747.13 cw(c6441.96,743.73) 6445.35,740.34 6407.69,702.68 ccw(c6411.08,699.28) 6407.69,695.89 6417.87,685.71 ccw(c6421.27,689.1) 6424.66,685.71 6462.32,723.37 cw(c6465.72,719.97) 6469.11,723.37 6479.29,713.19 cw(c6475.9,709.79) 6479.29,706.4 6446.45,673.55 ccw(c6449.84,670.16) 6446.45,666.76 6456.63,656.58 ccw(c6460.02,659.98) 6463.42,656.58 6478.58,671.75 cw(c6481.98,668.36) 6485.37,671.75 6515.57,641.55 7042.95,114.17 7185.04,114.17 7240.16,59.06 7329.66,59.06 v1(7355.86,32.86)
  L10-BOT w4: v1(2858.27,2771.34) 3465.07,2771.34 3638.33,2598.08 4527.9,2598.08 4555.68,2570.31 v1(4585.94,2570.31)
SZG_PORTG_S3: J5.18 MC3.96 | length 6621.1
  L1-TOP w4: MC3.96@2720.08,3001.97 2753.18,3001.97 2769.59,2985.56 2807.41,2985.56 2816.16,2976.81 2841.77,2976.81 v1(2858.27,2960.32)
  L8-SIG w5: v1(4719.57,2703.93) 4762.08,2661.42 4887.53,2661.42 6584.38,964.57 6594.49,964.57 6596.99,964.57 ccw(c6596.99,969.57) 6601.99,969.57 6601.99,984.57 cw(c6606.99,984.57) 6606.99,989.57 6621.99,989.57 cw(c6621.99,984.57) 6626.99,984.57 6626.99,925.95 ccw(c6631.99,925.95) 6631.99,920.95 6646.99,920.95 ccw(c6646.99,925.95) 6651.99,925.95 6651.99,984.57 cw(c6656.99,984.57) 6656.99,989.57 6671.99,989.57 cw(c6671.99,984.57) 6676.99,984.57 6676.99,925.95 ccw(c6681.99,925.95) 6681.99,920.95 6696.99,920.95 ccw(c6696.99,925.95) 6701.99,925.95 6701.99,984.57 cw(c6706.99,984.57) 6706.99,989.57 6721.99,989.57 cw(c6721.99,984.57) 6726.99,984.57 6726.99,925.95 ccw(c6731.99,925.95) 6731.99,920.95 6746.99,920.95 ccw(c6746.99,925.95) 6751.99,925.95 6751.99,984.57 cw(c6756.99,984.57) 6756.99,989.57 6771.99,989.57 cw(c6771.99,984.57) 6776.99,984.57 6776.99,925.95 ccw(c6781.99,925.95) 6781.99,920.95 6796.99,920.95 ccw(c6796.99,925.95) 6801.99,925.95 6801.99,984.57 cw(c6806.99,984.57) 6806.99,989.57 6821.99,989.57 cw(c6821.99,984.57) 6826.99,984.57 6826.99,925.95 ccw(c6831.99,925.95) 6831.99,920.95 6846.99,920.95 ccw(c6846.99,925.95) 6851.99,925.95 6851.99,977.72 cw(c6856.99,977.72) 6856.99,982.72 6871.99,982.72 cw(c6871.99,977.72) 6876.99,977.72 6876.99,969.57 ccw(c6881.99,969.57) 6881.99,964.57 6905.51,964.57 6913.14,964.57 7338.58,539.12 7338.58,314.96 7355.86,297.69 v1(7355.86,258.84)
  L10-BOT w4: v1(2858.27,2960.32) 3599.53,2960.32 3835.44,2724.41 4519.68,2724.41 4532.24,2736.96 4709.86,2736.96 4719.57,2727.26 v1(4719.57,2703.93)
SZG_PORTG_S4: J5.19 MC3.86 | length 6621.1
  L1-TOP w4: MC3.86@2720.08,2903.54 2769.52,2903.54 2822.23,2850.83 2841.77,2850.83 v1(2858.27,2834.33)
  L8-SIG w4: v1(4630.48,2614.85) 4669.85,2575.48 4837.45,2575.48 6606.07,806.86 6624.45,788.47 cw(c6621.06,785.08) 6624.45,781.68 6587.35,744.58 ccw(c6590.75,741.19) 6587.35,737.79 6597.53,727.61 ccw(c6600.93,731) 6604.32,727.61 6641.86,765.14 cw(c6645.25,761.75) 6648.64,765.14 6658.83,754.96 cw(c6655.43,751.57) 6658.83,748.17 6621.29,710.64 ccw(c6624.69,707.25) 6621.29,703.85 6631.47,693.67 ccw(c6634.87,697.06) 6638.26,693.67 6675.8,731.2 cw(c6679.19,727.81) 6682.58,731.2 6692.77,721.02 cw(c6689.37,717.63) 6692.77,714.23 6655.23,676.7 ccw(c6658.63,673.3) 6655.23,669.91 6665.42,659.73 ccw(c6668.81,663.12) 6672.2,659.73 6709.74,697.26 cw(c6713.13,693.87) 6716.53,697.26 6726.71,687.08 cw(c6723.31,683.68) 6726.71,680.29 6689.17,642.76 ccw(c6692.57,639.36) 6689.17,635.97 6699.36,625.79 ccw(c6702.75,629.18) 6706.15,625.79 6743.68,663.32 cw(c6747.07,659.93) 6750.47,663.32 6760.65,653.14 cw(c6757.25,649.74) 6760.65,646.35 6723.12,608.82 ccw(c6726.51,605.42) 6723.12,602.03 6733.3,591.85 ccw(c6736.69,595.24) 6740.09,591.85 6777.62,629.38 cw(c6781.01,625.98) 6784.41,629.38 6794.59,619.2 cw(c6791.2,615.8) 6794.59,612.41 6776.66,594.48 ccw(c6780.06,591.09) 6776.66,587.69 6786.85,577.51 ccw(c6790.24,580.91) 6793.63,577.51 6811.13,595.01 cw(c6814.52,591.61) 6817.92,595.01 6832.45,580.48 6838.58,574.34 6838.58,374.63 7055.73,157.48 7200.79,157.48 7263.78,94.49 7335.17,94.49 v1(7375.54,134.86)
  L10-BOT w4: v1(2858.27,2834.33) 3512.32,2834.33 3709.2,2637.45 4546.9,2637.45 4557.36,2647.91 4620.75,2647.91 4630.48,2638.18 v1(4630.48,2614.85)
SZG_PORTG_S5: J5.20 MC3.98 | length 6621.1
  L1-TOP w4: MC3.98@2720.08,3021.65 2762.15,3021.65 2775.5,3008.31 2841.77,3008.31 v1(2858.27,2991.81)
  L8-SIG w5: v1(4741.84,2726.2) 4783,2685.04 4904.68,2685.04 6530.67,1059.06 6535.43,1059.06 6537.93,1059.06 ccw(c6537.93,1064.06) 6542.93,1064.06 6542.93,1099.15 cw(c6547.93,1099.15) 6547.93,1104.15 6562.93,1104.15 cw(c6562.93,1099.15) 6567.93,1099.15 6567.93,1039.06 ccw(c6572.93,1039.06) 6572.93,1034.06 6587.93,1034.06 ccw(c6587.93,1039.06) 6592.93,1039.06 6592.93,1099.15 cw(c6597.93,1099.15) 6597.93,1104.15 6612.93,1104.15 cw(c6612.93,1099.15) 6617.93,1099.15 6617.93,1039.06 ccw(c6622.93,1039.06) 6622.93,1034.06 6637.93,1034.06 ccw(c6637.93,1039.06) 6642.93,1039.06 6642.93,1099.15 cw(c6647.93,1099.15) 6647.93,1104.15 6662.93,1104.15 cw(c6662.93,1099.15) 6667.93,1099.15 6667.93,1039.06 ccw(c6672.93,1039.06) 6672.93,1034.06 6687.93,1034.06 ccw(c6687.93,1039.06) 6692.93,1039.06 6692.93,1099.15 cw(c6697.93,1099.15) 6697.93,1104.15 6712.93,1104.15 cw(c6712.93,1099.15) 6717.93,1099.15 6717.93,1039.06 ccw(c6722.93,1039.06) 6722.93,1034.06 6737.93,1034.06 ccw(c6737.93,1039.06) 6742.93,1039.06 6742.93,1099.15 cw(c6747.93,1099.15) 6747.93,1104.15 6762.93,1104.15 cw(c6762.93,1099.15) 6767.93,1099.15 6767.93,1039.06 ccw(c6772.93,1039.06) 6772.93,1034.06 6787.93,1034.06 ccw(c6787.93,1039.06) 6792.93,1039.06 6792.93,1094.75 cw(c6797.93,1094.75) 6797.93,1099.75 6812.93,1099.75 cw(c6812.93,1094.75) 6817.93,1094.75 6817.93,1064.06 ccw(c6822.93,1064.06) 6822.93,1059.06 6857.81,1059.06 6859.43,1059.06 7375.54,542.94 v1(7375.54,360.84)
  L10-BOT w4: v1(2858.27,2991.81) 3622.36,2991.81 3870.08,2744.09 4507.87,2744.09 4522.72,2758.95 4732.42,2758.95 4741.84,2749.53 v1(4741.84,2726.2)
